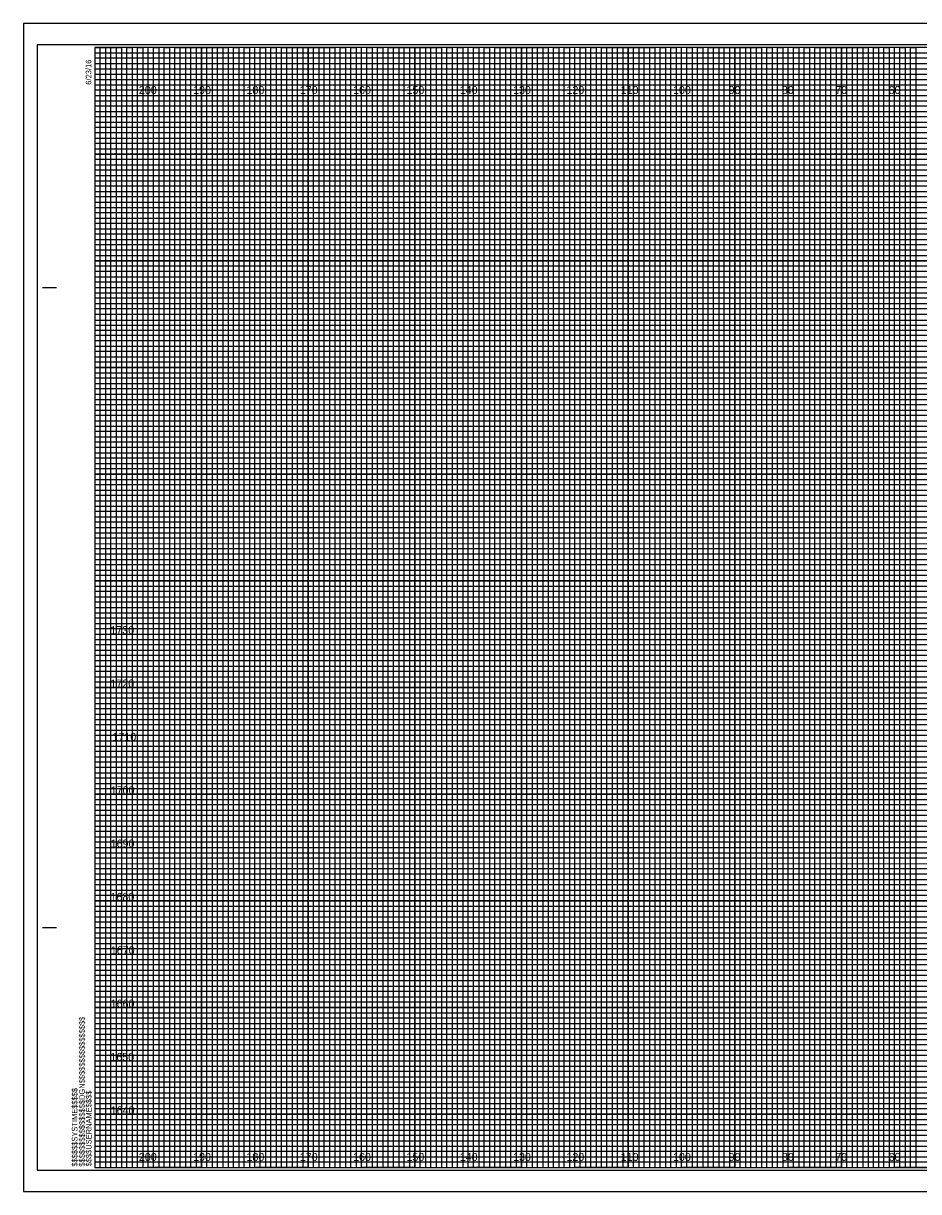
# Model space of a CAD drawing. Extents: x -3334 to 0, y 84 to 12624.
# Drawn here: x -711.6 to -543.7, y 744.2 to 963.2 of the extents above; entities that cross this region are included whole.
import ezdxf

# ---------------------------------------------------------------- set-up
doc = ezdxf.new("R2010")
doc.units = 0
for name, color, linetype in [('Old_Level_62', 7, 'Continuous'), ('Pattern 1', 7, 'Continuous'), ('Pattern 18', 7, 'Continuous'), ('Pattern 4', 7, 'Continuous'), ('Pattern 5', 7, 'Continuous'), ('Prop Dimension', 7, 'Continuous'), ('Prop Horizontal Alignment', 7, 'Continuous'), ('Raster_Level_0', 7, 'Continuous'), ('Scratch_Level_0', 7, 'Continuous'), ('Scratch_Level_3', 7, 'Continuous'), ('Scratch_Level_5', 7, 'Continuous')]:
    doc.layers.add(name, color=color, linetype=linetype)

msp = doc.modelspace()

# ---------------------------------------------------------------- linework, layer by layer
at = {"layer": 'Old_Level_62'}
for p, q in [((-708.04, 913.74), (-705.54, 913.74)), ((-707.94, 913.74), (-705.44, 913.74)), ((-708.04, 793.74), (-705.54, 793.74)), ((-707.94, 793.74), (-705.44, 793.74)), ((-698.24, 748.74), (-698.24, 748.74)), ((-698.24, 748.74), (-698.24, 748.74)), ((-698.24, 748.74), (-698.24, 748.74)), ((-698.24, 748.74), (-698.24, 748.74)), ((-698.24, 748.74), (-698.24, 748.74)), ((-698.24, 748.74), (-698.24, 748.74)), ((-698.24, 748.74), (-698.24, 748.74))]:
    msp.add_line(p, q, dxfattribs=at)
msp.add_lwpolyline([(-378.24, 958.74), (-698.24, 958.74), (-698.24, 748.74), (-378.24, 748.74)], close=True, dxfattribs=at)
at = {"layer": 'Pattern 18'}
msp.add_lwpolyline([(-711.64, 744.24), (-374.94, 744.24), (-374.94, 963.24), (-711.64, 963.24)], close=True, dxfattribs=at)
at = {"layer": 'Pattern 4'}
for p, q in [((-698.24, 957.74), (-438.24, 957.74)), ((-438.24, 956.72), (-698.24, 956.72)), ((-698.24, 956.72), (-698.24, 955.74)), ((-698.24, 955.74), (-438.24, 955.74)), ((-438.24, 954.63), (-698.24, 954.63)), ((-698.24, 954.63), (-698.24, 952.74)), ((-698.24, 952.74), (-378.24, 952.74))]:
    msp.add_line(p, q, dxfattribs=at)
for points in [[(-698.24, 951.74), (-428.24, 951.74), (-378.24, 951.74), (-378.24, 950.74), (-698.24, 950.74)], [(-698.24, 949.74), (-378.24, 949.74), (-378.24, 947.74), (-698.24, 947.74)], [(-698.24, 946.74), (-378.24, 946.74), (-378.24, 945.74), (-698.24, 945.72)], [(-698.24, 944.74), (-378.24, 944.74), (-378.24, 942.74), (-698.24, 942.74)], [(-698.24, 941.74), (-378.24, 941.74), (-378.24, 940.74), (-698.24, 940.74)], [(-698.24, 939.74), (-378.24, 939.74), (-378.24, 937.74), (-698.24, 937.74)], [(-698.24, 936.74), (-378.24, 936.74), (-378.24, 935.74), (-698.24, 935.74)], [(-698.24, 934.74), (-378.24, 934.74), (-378.24, 932.74), (-698.24, 932.74)], [(-698.24, 931.74), (-378.24, 931.74), (-378.24, 930.74), (-698.24, 930.74)], [(-698.24, 929.74), (-378.24, 929.74), (-378.24, 927.74), (-698.24, 927.74)], [(-698.24, 926.74), (-378.24, 926.74), (-378.24, 925.74), (-698.24, 925.74)], [(-698.24, 924.74), (-378.24, 924.74), (-378.24, 922.69), (-378.24, 921.74), (-378.24, 920.74), (-698.24, 920.74)], [(-698.24, 922.74), (-378.24, 922.74), (-378.24, 921.74), (-698.24, 921.74)], [(-698.24, 919.74), (-378.24, 919.74), (-378.24, 917.74), (-698.24, 917.77)], [(-698.24, 917.77), (-378.24, 917.74), (-378.24, 916.74), (-698.24, 916.74)], [(-698.24, 915.74), (-378.24, 915.74), (-378.24, 914.74), (-698.24, 914.74)], [(-698.24, 912.74), (-378.24, 912.74), (-378.24, 911.74), (-698.24, 911.74)], [(-698.24, 910.74), (-378.24, 910.74), (-378.24, 909.74), (-698.24, 909.74)], [(-698.31, 907.63), (-378.24, 907.63), (-378.24, 906.62), (-698.31, 906.62)], [(-698.24, 905.74), (-378.24, 905.74), (-378.24, 904.74), (-698.24, 904.74)], [(-698.24, 902.74), (-378.24, 902.74), (-378.24, 901.74), (-698.24, 901.74)], [(-698.24, 900.74), (-378.24, 900.74), (-378.24, 899.74), (-698.24, 899.74)], [(-698.24, 897.74), (-378.24, 897.74), (-378.24, 896.74), (-698.24, 896.74)], [(-698.24, 895.74), (-378.24, 895.74), (-378.24, 894.74), (-698.24, 894.74)], [(-698.24, 892.74), (-378.24, 892.74), (-378.24, 891.74), (-698.24, 891.74)], [(-698.24, 890.74), (-378.24, 890.74), (-378.24, 889.74), (-698.24, 889.74)], [(-698.24, 887.74), (-378.24, 887.74), (-378.25, 886.72), (-698.24, 886.74)], [(-698.24, 885.74), (-378.24, 885.74), (-378.24, 884.74), (-698.24, 884.74)], [(-698.24, 882.74), (-378.24, 882.74), (-378.24, 881.74), (-698.24, 881.74)], [(-698.24, 880.74), (-378.24, 880.74), (-378.24, 879.74), (-698.24, 879.74)], [(-698.24, 877.74), (-378.24, 877.74), (-378.24, 876.74), (-698.24, 876.74)], [(-698.24, 875.74), (-378.24, 875.74), (-378.24, 874.74), (-698.24, 874.74)], [(-698.24, 872.74), (-378.24, 872.74), (-378.24, 871.74), (-698.24, 871.74)], [(-698.24, 870.74), (-378.24, 870.74), (-378.24, 869.74), (-698.24, 869.74)], [(-698.24, 867.74), (-378.24, 867.74), (-378.24, 866.74), (-698.24, 866.74)], [(-698.24, 865.73), (-378.17, 865.65), (-378.24, 864.74), (-698.24, 864.74)], [(-698.24, 862.74), (-378.24, 862.74), (-378.24, 861.74), (-698.24, 861.74)], [(-698.24, 860.74), (-378.24, 860.74), (-378.24, 859.74), (-698.24, 859.74)], [(-698.24, 857.74), (-378.24, 857.74), (-378.24, 856.74), (-698.24, 856.74)], [(-698.24, 855.74), (-378.24, 855.74), (-378.24, 854.74), (-698.24, 854.74)], [(-698.24, 852.74), (-378.24, 852.74), (-378.24, 851.74), (-698.24, 851.74)], [(-698.24, 850.74), (-378.24, 850.74), (-378.24, 849.74), (-698.24, 849.74)], [(-698.24, 847.74), (-378.24, 847.74), (-378.24, 846.74), (-698.24, 846.74)], [(-698.24, 845.74), (-378.24, 845.74), (-378.24, 844.74), (-698.24, 844.74)], [(-698.24, 842.74), (-378.24, 842.74), (-378.24, 841.74), (-698.24, 841.74)], [(-698.24, 840.74), (-378.24, 840.74), (-378.24, 839.74), (-698.24, 839.74)], [(-698.24, 837.74), (-378.24, 837.74), (-378.24, 836.74), (-698.24, 836.74)], [(-698.24, 835.74), (-378.24, 835.74), (-378.24, 834.74), (-698.24, 834.74)], [(-698.24, 832.74), (-378.24, 832.74), (-378.24, 831.74), (-698.24, 831.74)], [(-698.24, 830.74), (-378.24, 830.74), (-378.24, 829.74), (-698.24, 829.74)], [(-698.24, 827.74), (-378.24, 827.74), (-378.25, 826.72), (-698.24, 826.74)], [(-698.24, 825.74), (-378.24, 825.74), (-378.24, 824.74), (-698.24, 824.74)], [(-698.24, 822.74), (-378.24, 822.74), (-378.24, 821.74), (-698.24, 821.74)], [(-698.24, 820.74), (-378.24, 820.74), (-378.24, 819.74), (-698.24, 819.74)], [(-698.24, 817.74), (-378.24, 817.74), (-378.24, 816.74), (-698.24, 816.74)], [(-698.24, 815.74), (-378.24, 815.74), (-378.24, 814.74), (-698.24, 814.74)], [(-698.24, 812.74), (-378.24, 812.74), (-378.24, 811.74), (-698.24, 811.74)], [(-698.24, 810.74), (-378.24, 810.74), (-378.24, 809.74), (-698.24, 809.74)], [(-698.24, 807.74), (-378.24, 807.74), (-378.24, 806.74), (-698.24, 806.74)], [(-698.24, 805.73), (-378.17, 805.65), (-378.24, 804.74), (-698.24, 804.74)], [(-698.24, 802.74), (-378.24, 802.74), (-378.24, 801.74), (-698.24, 801.74)], [(-698.24, 800.74), (-378.24, 800.74), (-378.24, 799.74), (-698.24, 799.74)], [(-698.24, 797.74), (-378.24, 797.74), (-378.24, 796.74), (-698.24, 796.74)], [(-698.24, 795.74), (-378.24, 795.74), (-378.24, 794.74), (-698.24, 794.74)], [(-698.24, 792.74), (-378.24, 792.74), (-378.24, 791.74), (-698.24, 791.74)], [(-698.24, 790.74), (-378.24, 790.74), (-378.24, 789.74), (-698.24, 789.74)], [(-698.24, 787.74), (-378.24, 787.74), (-378.24, 786.74), (-698.24, 786.74)], [(-698.24, 785.74), (-378.24, 785.74), (-378.24, 784.74), (-698.24, 784.74)], [(-698.24, 782.74), (-378.24, 782.74), (-378.24, 781.74), (-698.24, 781.74)], [(-698.24, 780.74), (-378.24, 780.74), (-378.24, 779.74), (-698.24, 779.74)], [(-698.24, 777.74), (-378.24, 777.74), (-378.24, 776.74), (-698.24, 776.74)], [(-698.24, 775.74), (-378.24, 775.74), (-378.24, 774.74), (-698.24, 774.74)], [(-698.24, 772.74), (-378.24, 772.74), (-378.24, 771.74), (-698.24, 771.74)], [(-698.24, 770.74), (-378.24, 770.74), (-378.24, 769.74), (-698.24, 769.74)], [(-698.24, 767.74), (-378.24, 767.74), (-378.24, 766.74), (-698.24, 766.74)], [(-698.24, 765.74), (-378.24, 765.74), (-378.24, 764.74), (-698.24, 764.74)], [(-698.24, 762.74), (-378.24, 762.74), (-378.24, 761.74), (-698.24, 761.74)], [(-698.24, 760.74), (-378.24, 760.74), (-378.24, 759.74), (-698.24, 759.74)], [(-698.24, 757.74), (-378.24, 757.74), (-378.24, 756.74), (-698.24, 756.74)], [(-698.24, 755.74), (-378.24, 755.74), (-378.24, 754.74), (-698.24, 754.74)], [(-698.24, 752.74), (-378.24, 752.74), (-378.24, 751.74), (-698.24, 751.74)], [(-698.24, 750.74), (-378.24, 750.74), (-378.24, 749.74), (-698.24, 749.74)]]:
    msp.add_lwpolyline(points, dxfattribs=at)
at = {"layer": 'Pattern 5'}
for p, q in [((-374.94, 963.24), (-711.64, 963.24)), ((-711.64, 963.24), (-711.64, 744.24)), ((-711.64, 744.24), (-374.94, 744.24))]:
    msp.add_line(p, q, dxfattribs=at)
at = {"layer": 'Prop Dimension'}
for points in [[(-698.24, 748.74), (-697.24, 748.74), (-697.24, 958.74), (-696.24, 958.74), (-696.24, 748.74)], [(-696.24, 748.74), (-695.24, 748.74), (-695.24, 958.74), (-694.24, 958.74), (-694.24, 748.74)], [(-693.24, 748.74), (-692.24, 748.74), (-692.24, 958.74), (-691.24, 958.74), (-691.24, 748.74)], [(-691.24, 748.74), (-690.24, 748.74), (-690.24, 958.74), (-689.24, 958.74), (-689.24, 748.74)], [(-688.24, 748.74), (-687.24, 748.74), (-687.24, 958.74), (-686.24, 958.74), (-686.24, 748.74)], [(-686.24, 748.74), (-685.24, 748.74), (-685.24, 958.74), (-684.24, 958.74), (-684.24, 748.74)], [(-683.24, 748.74), (-682.24, 748.74), (-682.24, 958.74), (-681.24, 958.74), (-681.24, 748.74)], [(-681.24, 748.74), (-680.24, 748.74), (-680.24, 958.74), (-679.24, 958.74), (-679.24, 748.74)], [(-678.24, 748.74), (-677.24, 748.74), (-677.24, 958.74), (-676.24, 958.74), (-676.24, 748.74)], [(-676.24, 748.74), (-675.24, 748.74), (-675.24, 958.74), (-674.24, 958.74), (-674.24, 748.74)], [(-673.24, 748.74), (-672.24, 748.74), (-672.24, 958.74), (-671.24, 958.74), (-671.24, 748.74)], [(-671.24, 748.74), (-670.24, 748.74), (-670.24, 958.74), (-669.24, 958.74), (-669.24, 748.74)], [(-668.24, 748.74), (-667.24, 748.74), (-667.24, 958.74), (-666.24, 958.74), (-666.24, 748.74)], [(-666.24, 748.74), (-665.24, 748.74), (-665.24, 958.74), (-664.24, 958.74), (-664.24, 748.74)], [(-663.24, 748.74), (-662.24, 748.74), (-662.24, 958.74), (-661.24, 958.74), (-661.24, 748.74)], [(-661.24, 748.74), (-660.24, 748.74), (-660.24, 958.74), (-659.24, 958.74), (-659.24, 748.74)], [(-658.24, 748.74), (-657.24, 748.74), (-657.24, 958.74), (-656.24, 958.74), (-656.24, 748.74)], [(-656.24, 748.74), (-655.24, 748.74), (-655.24, 958.74), (-654.24, 958.74), (-654.24, 748.74)], [(-653.24, 748.74), (-652.24, 748.74), (-652.24, 958.74), (-651.24, 958.74), (-651.24, 748.74)], [(-651.24, 748.74), (-650.24, 748.74), (-650.24, 958.74), (-649.24, 958.74), (-649.24, 748.74)], [(-648.24, 748.74), (-647.24, 748.74), (-647.24, 958.74), (-646.24, 958.74), (-646.24, 748.74)], [(-646.24, 748.74), (-645.24, 748.74), (-645.24, 958.74), (-644.24, 958.74), (-644.24, 748.74)], [(-643.24, 748.74), (-642.24, 748.74), (-642.24, 958.74), (-641.24, 958.74), (-641.24, 748.74)], [(-641.24, 748.74), (-640.24, 748.74), (-640.24, 958.74), (-639.24, 958.74), (-639.24, 748.74)], [(-638.24, 748.74), (-637.24, 748.74), (-637.24, 958.74), (-636.24, 958.74), (-636.24, 748.74)], [(-636.24, 748.74), (-635.24, 748.74), (-635.24, 958.74), (-634.24, 958.74), (-634.24, 748.74)], [(-633.24, 748.74), (-632.24, 748.74), (-632.24, 958.74), (-631.24, 958.74), (-631.24, 748.74)], [(-631.24, 748.74), (-630.24, 748.74), (-630.24, 958.74), (-629.24, 958.74), (-629.24, 748.74)], [(-628.24, 748.74), (-627.24, 748.74), (-627.24, 958.74), (-626.24, 958.74), (-626.24, 748.74)], [(-626.24, 748.74), (-625.24, 748.74), (-625.24, 958.74), (-624.24, 958.74), (-624.24, 748.74)], [(-623.24, 748.74), (-622.24, 748.74), (-622.24, 958.74), (-621.24, 958.74), (-621.24, 748.74)], [(-621.24, 748.74), (-620.24, 748.74), (-620.24, 958.74), (-619.24, 958.74), (-619.24, 748.74)], [(-618.24, 748.74), (-617.24, 748.74), (-617.24, 958.74), (-616.24, 958.74), (-616.24, 748.74)], [(-616.24, 748.74), (-615.24, 748.74), (-615.24, 958.74), (-614.24, 958.74), (-614.24, 748.74)], [(-613.24, 748.74), (-612.24, 748.74), (-612.24, 958.74), (-611.24, 958.74), (-611.24, 748.74)], [(-611.24, 748.74), (-610.24, 748.74), (-610.24, 958.74), (-609.24, 958.74), (-609.24, 748.74)], [(-608.24, 748.74), (-607.24, 748.74), (-607.24, 958.74), (-606.24, 958.74), (-606.24, 748.74)], [(-606.24, 748.74), (-605.24, 748.74), (-605.24, 958.74), (-604.24, 958.74), (-604.24, 748.74)], [(-603.24, 748.74), (-602.24, 748.74), (-602.24, 958.74), (-601.24, 958.74), (-601.24, 748.74)], [(-601.24, 748.74), (-600.24, 748.74), (-600.24, 958.74), (-599.24, 958.74), (-599.24, 748.74)], [(-598.24, 748.74), (-597.24, 748.74), (-597.24, 958.74), (-596.24, 958.74), (-596.24, 748.74)], [(-596.24, 748.74), (-595.24, 748.74), (-595.24, 958.74), (-594.24, 958.74), (-594.24, 748.74)], [(-593.24, 748.74), (-592.24, 748.74), (-592.24, 958.74), (-591.24, 958.74), (-591.24, 748.74)], [(-591.24, 748.74), (-590.24, 748.74), (-590.24, 958.74), (-589.24, 958.74), (-589.24, 748.74)], [(-588.24, 748.74), (-587.24, 748.74), (-587.24, 958.74), (-586.24, 958.74), (-586.24, 748.74)], [(-586.24, 748.74), (-585.24, 748.74), (-585.24, 958.74), (-584.24, 958.74), (-584.24, 748.74)], [(-583.24, 748.74), (-582.24, 748.74), (-582.24, 958.74), (-581.24, 958.74), (-581.24, 748.74)], [(-581.24, 748.74), (-580.24, 748.74), (-580.24, 958.74), (-579.24, 958.74), (-579.24, 748.74)], [(-578.24, 748.74), (-577.24, 748.74), (-577.24, 958.74), (-576.24, 958.74), (-576.24, 748.74)], [(-576.24, 748.74), (-575.24, 748.74), (-575.24, 958.74), (-574.24, 958.74), (-574.24, 748.74)], [(-573.24, 748.74), (-572.24, 748.74), (-572.24, 958.74), (-571.24, 958.74), (-571.24, 748.74)], [(-571.24, 748.74), (-570.24, 748.74), (-570.24, 958.74), (-569.24, 958.74), (-569.24, 748.74)], [(-568.24, 748.74), (-567.24, 748.74), (-567.24, 958.74), (-566.24, 958.74), (-566.24, 748.74)], [(-566.24, 748.74), (-565.24, 748.74), (-565.24, 958.74), (-564.24, 958.74), (-564.24, 748.74)], [(-563.24, 748.74), (-562.24, 748.74), (-562.24, 958.74), (-561.24, 958.74), (-561.24, 748.74)], [(-561.24, 748.74), (-560.24, 748.74), (-560.24, 958.74), (-559.24, 958.74), (-559.24, 748.74)], [(-558.24, 748.74), (-557.24, 748.74), (-557.24, 958.74), (-556.24, 958.74), (-556.24, 748.74)], [(-556.24, 748.74), (-555.24, 748.74), (-555.24, 958.74), (-554.24, 958.74), (-554.24, 748.74)], [(-553.24, 748.74), (-552.24, 748.74), (-552.24, 958.74), (-551.24, 958.74), (-551.24, 748.74)], [(-551.24, 748.74), (-550.24, 748.74), (-550.24, 958.74), (-549.24, 958.74), (-549.24, 748.74)], [(-548.24, 748.74), (-547.24, 748.74), (-547.24, 958.74), (-546.24, 958.74), (-546.24, 748.74)], [(-546.24, 748.74), (-545.24, 748.74), (-545.24, 958.74), (-544.24, 958.74), (-544.24, 748.74)]]:
    msp.add_lwpolyline(points, dxfattribs=at)
at = {"layer": 'Prop Horizontal Alignment'}
for points in [[(-698.24, 958.74), (-693.24, 958.74), (-693.24, 748.74), (-683.24, 748.74), (-683.24, 958.74), (-673.24, 958.74), (-673.24, 748.74), (-663.24, 748.74), (-663.24, 958.74), (-653.24, 958.74), (-653.24, 748.74), (-643.24, 748.74), (-643.24, 958.74), (-633.24, 958.74), (-633.24, 748.74), (-623.24, 748.74), (-623.24, 958.74), (-613.24, 958.74), (-613.24, 748.74), (-603.24, 748.74), (-603.24, 958.74), (-593.24, 958.74), (-593.24, 748.74), (-583.24, 748.74), (-583.24, 958.74), (-573.24, 958.74), (-573.24, 748.74), (-563.24, 748.74), (-563.24, 958.74), (-553.24, 958.74), (-553.24, 748.74), (-543.24, 748.74)], [(-698.24, 953.74), (-423.24, 953.74)], [(-698.24, 933.74), (-378.24, 933.74), (-378.24, 943.74), (-698.24, 943.74)], [(-698.24, 913.74), (-378.24, 913.74), (-378.24, 923.74), (-698.24, 923.74)], [(-698.24, 893.74), (-378.24, 893.74), (-378.24, 903.74), (-698.24, 903.74)], [(-698.24, 873.74), (-378.24, 873.74), (-378.24, 883.74), (-698.24, 883.74)], [(-698.24, 853.74), (-378.24, 853.74), (-378.24, 863.74), (-698.24, 863.74)], [(-698.24, 833.74), (-378.24, 833.74), (-378.24, 843.74), (-698.24, 843.74)], [(-698.24, 813.74), (-378.24, 813.74), (-378.24, 823.74), (-698.24, 823.74)], [(-698.24, 793.74), (-378.24, 793.74), (-378.24, 803.74), (-698.24, 803.74)], [(-698.24, 773.74), (-378.24, 773.74), (-378.24, 783.74), (-698.24, 783.74)], [(-698.24, 753.74), (-378.24, 753.74), (-378.24, 763.74), (-698.24, 763.74)]]:
    msp.add_lwpolyline(points, dxfattribs=at)
at = {"layer": 'Scratch_Level_0'}
for p, q in [((-688.24, 748.74), (-688.24, 958.74)), ((-678.24, 748.74), (-678.24, 958.74)), ((-668.24, 748.74), (-668.24, 958.74)), ((-658.24, 748.74), (-658.24, 958.74)), ((-648.24, 748.74), (-648.24, 958.74)), ((-638.24, 748.74), (-638.24, 958.74)), ((-628.24, 748.74), (-628.24, 958.74)), ((-618.24, 748.74), (-618.24, 958.74)), ((-608.24, 748.74), (-608.24, 958.74)), ((-598.24, 748.74), (-598.24, 958.74)), ((-588.24, 748.74), (-588.24, 958.74)), ((-578.24, 748.74), (-578.24, 958.74)), ((-568.24, 748.74), (-568.24, 958.74)), ((-558.24, 748.74), (-558.24, 958.74)), ((-548.24, 748.74), (-548.24, 958.74)), ((-698.24, 948.74), (-378.24, 948.74)), ((-698.24, 938.74), (-378.24, 938.74)), ((-698.24, 928.74), (-378.24, 928.74)), ((-698.24, 918.74), (-378.24, 918.74)), ((-698.24, 908.74), (-378.24, 908.74)), ((-698.24, 898.74), (-378.24, 898.74)), ((-698.24, 888.74), (-378.24, 888.74)), ((-698.24, 878.74), (-378.24, 878.74)), ((-698.24, 868.74), (-378.24, 868.74)), ((-698.24, 858.74), (-378.24, 858.74)), ((-698.24, 848.74), (-378.24, 848.74)), ((-698.24, 838.74), (-378.24, 838.74)), ((-698.24, 828.74), (-378.24, 828.74)), ((-698.24, 818.74), (-378.24, 818.74)), ((-698.24, 808.74), (-378.24, 808.74)), ((-698.24, 798.74), (-378.24, 798.74)), ((-698.24, 788.74), (-378.24, 788.74)), ((-698.24, 778.74), (-378.24, 778.74)), ((-698.24, 768.74), (-378.24, 768.74)), ((-698.24, 758.74), (-378.24, 758.74))]:
    msp.add_line(p, q, dxfattribs=at)
at = {"layer": 'Scratch_Level_3'}
for p, q in [((-688.24, 958.74), (-698.24, 958.74)), ((-688.24, 748.74), (-688.24, 958.74)), ((-668.24, 958.74), (-678.24, 958.74)), ((-678.24, 958.74), (-678.24, 748.74)), ((-668.24, 748.74), (-668.24, 958.74)), ((-648.24, 958.74), (-658.24, 958.74)), ((-658.24, 958.74), (-658.24, 748.74)), ((-648.24, 748.74), (-648.24, 958.74)), ((-628.24, 958.74), (-638.24, 958.74)), ((-638.24, 958.74), (-638.24, 748.74)), ((-628.24, 748.74), (-628.24, 958.74)), ((-608.24, 958.74), (-618.24, 958.74)), ((-618.24, 958.74), (-618.24, 748.74)), ((-608.24, 748.74), (-608.24, 958.74)), ((-588.24, 958.74), (-598.24, 958.74)), ((-598.24, 958.74), (-598.24, 748.74)), ((-588.24, 748.74), (-588.24, 958.74)), ((-568.24, 958.74), (-578.24, 958.74)), ((-578.24, 958.74), (-578.24, 748.74)), ((-568.24, 748.74), (-568.24, 958.74)), ((-548.24, 958.74), (-558.24, 958.74)), ((-558.24, 958.74), (-558.24, 748.74)), ((-548.24, 748.74), (-548.24, 958.74)), ((-678.24, 748.74), (-688.24, 748.74)), ((-658.24, 748.74), (-668.24, 748.74)), ((-638.24, 748.74), (-648.24, 748.74)), ((-618.24, 748.74), (-628.24, 748.74)), ((-598.24, 748.74), (-608.24, 748.74)), ((-578.24, 748.74), (-588.24, 748.74)), ((-558.24, 748.74), (-568.24, 748.74)), ((-538.24, 748.74), (-548.24, 748.74))]:
    msp.add_line(p, q, dxfattribs=at)
for points in [[(-698.24, 948.74), (-378.24, 948.74), (-378.24, 938.74), (-698.24, 938.74)], [(-698.24, 928.74), (-378.24, 928.74), (-378.24, 918.74), (-698.24, 918.74)], [(-698.24, 908.74), (-378.24, 908.74), (-378.24, 898.74), (-698.24, 898.74)], [(-698.24, 888.74), (-378.24, 888.74), (-378.24, 878.74), (-698.24, 878.74)], [(-698.24, 868.74), (-378.24, 868.74), (-378.24, 858.74), (-698.24, 858.74)], [(-698.24, 848.74), (-378.24, 848.74), (-378.24, 838.74), (-698.24, 838.74)], [(-698.24, 828.74), (-378.24, 828.74), (-378.24, 818.74), (-698.24, 818.74)], [(-698.24, 808.74), (-378.24, 808.74), (-378.24, 798.74), (-698.24, 798.74)], [(-698.24, 788.74), (-378.24, 788.74), (-378.24, 778.74), (-698.24, 778.74)], [(-698.24, 768.74), (-378.24, 768.74), (-378.24, 758.74), (-698.24, 758.74)]]:
    msp.add_lwpolyline(points, dxfattribs=at)
at = {"layer": 'Scratch_Level_5'}
msp.add_lwpolyline([(-709.04, 748.24), (-375.84, 748.24), (-375.84, 959.24), (-709.04, 959.24)], close=True, dxfattribs=at)

# ---------------------------------------------------------------- texts
at = {"layer": 'Old_Level_62'}
for s, p in [('6/23/16', (-698.89, 951.74)), ('$$$$$$$$$$$$$$$$DGN$$$$$$$$$$$$$$$$', (-700.12, 748.92)), ('$$$$$$SYSTIME$$$$$', (-701.5, 748.92)), ('$$$$USERNAME$$$$', (-698.86, 748.97))]:
    msp.add_text(s, height=1.05, rotation=90, dxfattribs=at).set_placement(p)
at = {"layer": 'Pattern 1'}
for s, p in [('1730', (-695.32, 848.74)), ('1720', (-695.31, 838.74)), ('1710', (-694.93, 828.74)), ('1700', (-695.26, 818.74)), ('1690', (-695.27, 808.74)), ('1680', (-695.3, 798.74)), ('1670', (-695.24, 788.74)), ('1660', (-695.27, 778.74)), ('1650', (-695.32, 768.74)), ('1640', (-695.27, 758.74))]:
    msp.add_text(s, height=1.5, dxfattribs=at).set_placement(p)
at = {"layer": 'Raster_Level_0'}
for s, p in [('200', (-689.98, 949.99)), ('190', (-679.8, 949.99)), ('180', (-669.8, 949.99)), ('170', (-659.8, 949.99)), ('160', (-649.8, 949.99)), ('150', (-639.8, 949.99)), ('140', (-629.8, 949.99)), ('130', (-619.8, 949.99)), ('120', (-609.8, 949.99)), ('110', (-599.62, 949.99)), ('100', (-589.8, 949.99)), ('90', (-579.38, 949.99)), ('80', (-569.38, 949.99)), ('70', (-559.38, 949.99)), ('60', (-549.38, 949.99)), ('200', (-689.98, 749.99)), ('190', (-679.8, 749.99)), ('180', (-669.8, 749.99)), ('170', (-659.8, 749.99)), ('160', (-649.8, 749.99)), ('150', (-639.8, 749.99)), ('140', (-629.8, 749.99)), ('130', (-619.8, 749.99)), ('120', (-609.8, 749.99)), ('110', (-599.62, 749.99)), ('100', (-589.8, 749.99)), ('90', (-579.38, 749.99)), ('80', (-569.38, 749.99)), ('70', (-559.38, 749.99)), ('60', (-549.38, 749.99))]:
    msp.add_text(s, height=1.5, dxfattribs=at).set_placement(p)

doc.saveas('drawing.dxf')
